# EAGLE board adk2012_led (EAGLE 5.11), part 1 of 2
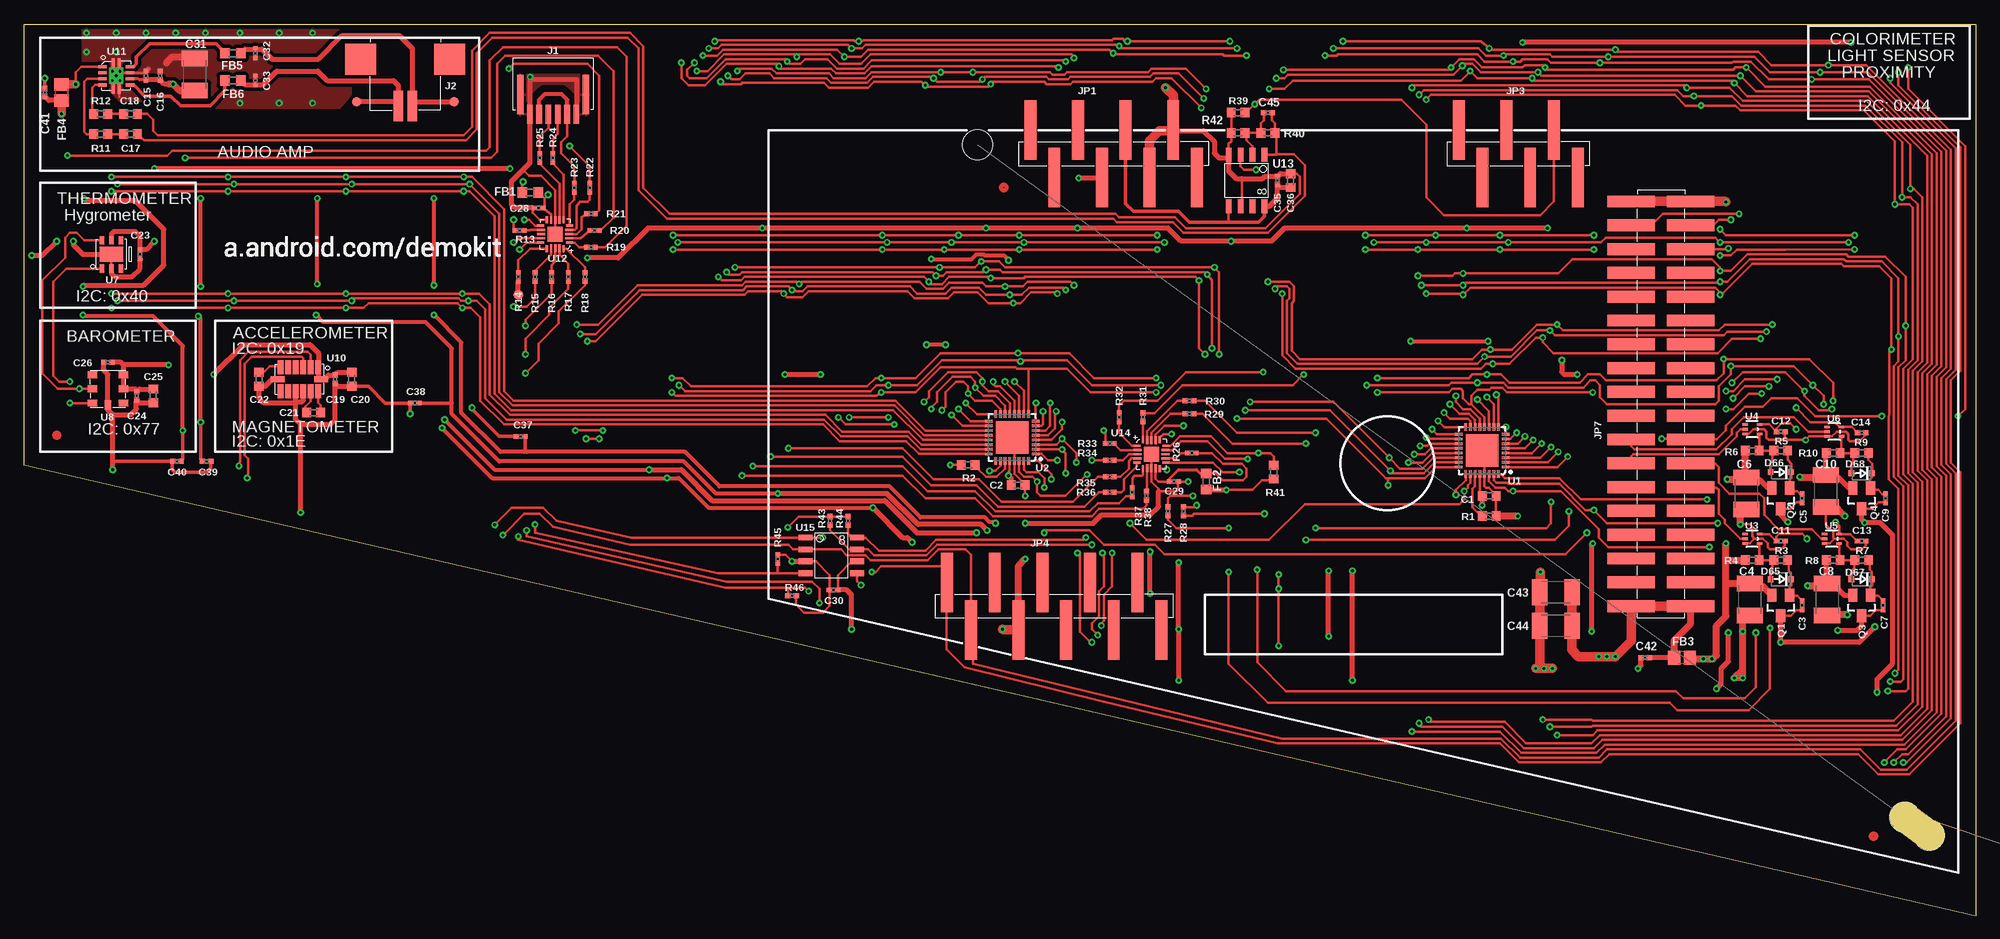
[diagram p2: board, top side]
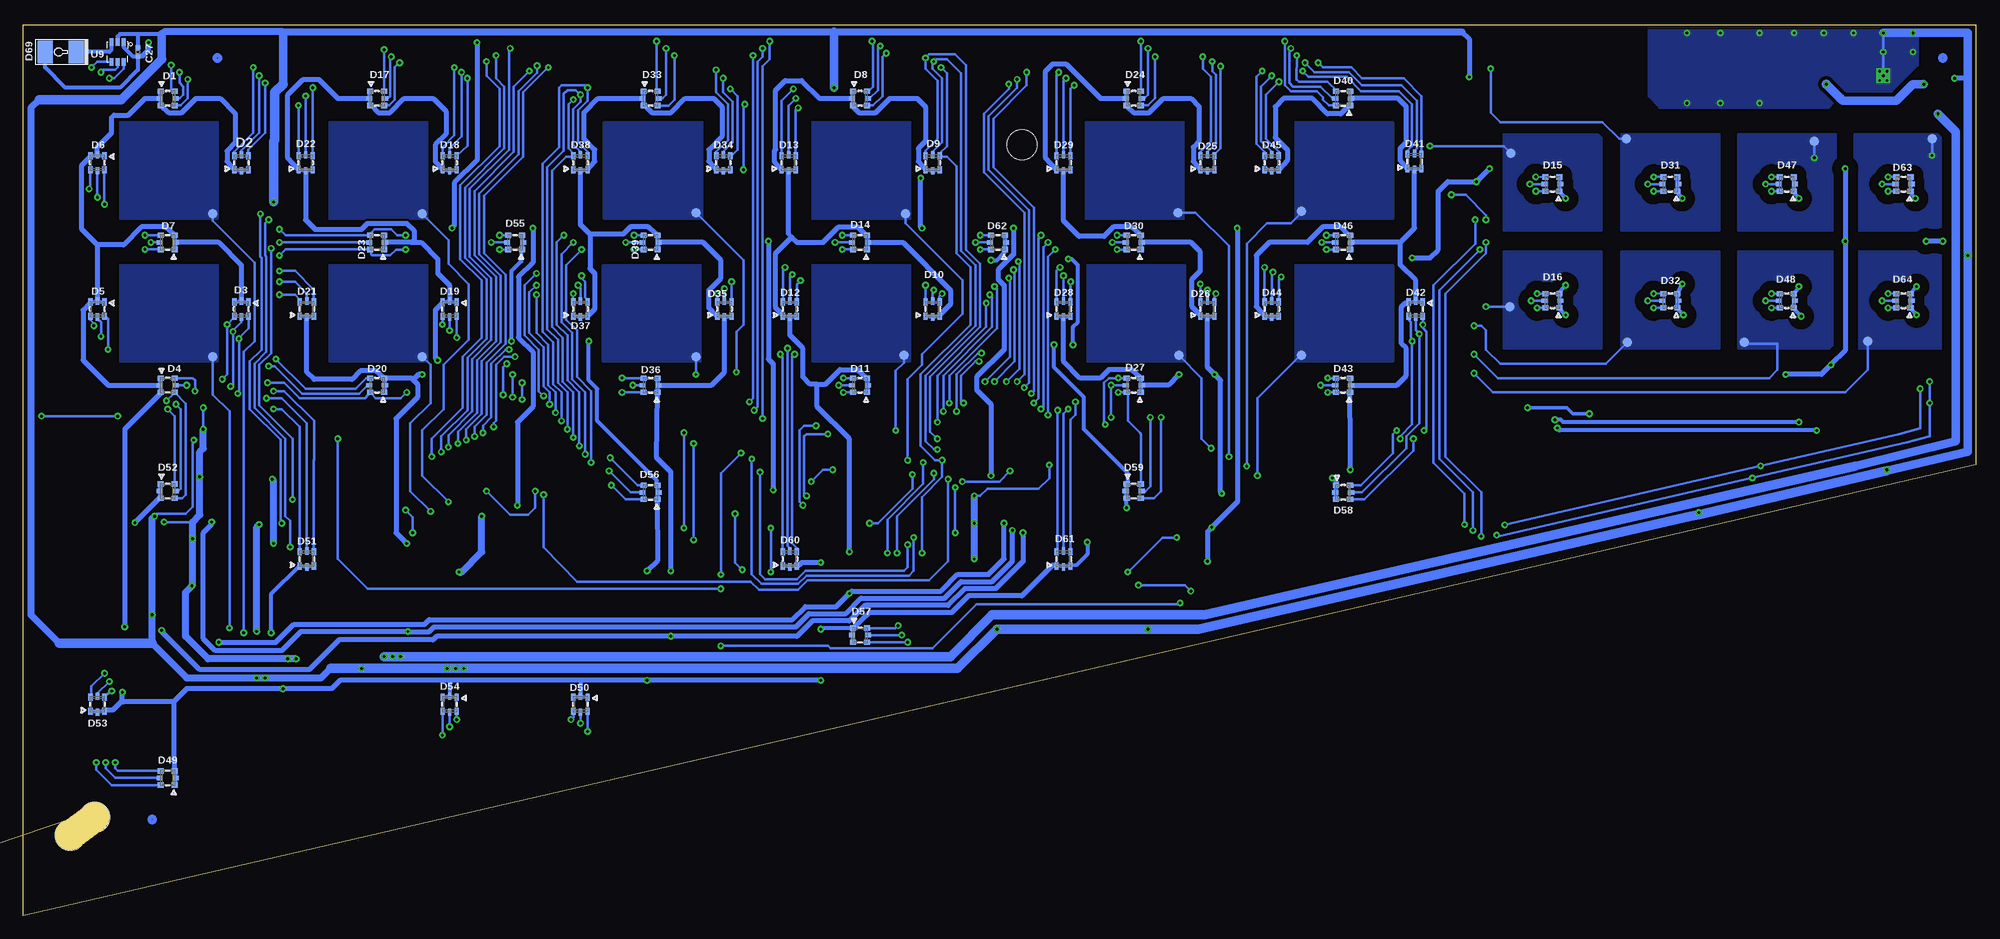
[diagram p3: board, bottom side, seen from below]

Size 208.38 x 95.07 mm. Coordinates in mm from the lower left corner, seen from the top.
Outline: 0,48.11 208.38,0 208.38,95.07 0,95.07 0,48.11
Copper layers (1*16): Top 0.035mm / dielectric 1.5mm / Bottom 0.035mm
Design rules "default *": minimum track width 6mil, minimum drill 10mil, track to track 6mil, track to pad 6mil, pad to pad 6mil, via to via 6mil, smd to smd 6mil, copper to edge 5mil, drill to drill 8mil, minimum pad ring 6mil, minimum via ring 8mil, stop-mask expansion 4mil, vias tented up to drill 12mil, thermal gap 10mil
Net classes: 0 default: width 0.152 mm, drill 0.305 mm, clearance 0.152 mm
Holes 3.2 mm at 101.8,82.25 203.4,8.59 200.77,10.49 9.48,-18.69
Holes 0.3 mm at 9.48,-13.61
Milling: 2 lines

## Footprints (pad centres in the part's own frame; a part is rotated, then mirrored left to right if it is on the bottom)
C0603U = smd 0.94 x 1.016: 1 -0.737,0; 2 0.737,0
C0402U = smd 0.584 x 0.508: 1 -0.445,0; 2 0.445,0
C1210U = smd 1.651 x 2.794: 1 -1.714,0; 2 1.714,0
LRTB-98G = smd 0.5 x 0.7: 1 -0.75,-0.75; 3 0.75,-0.75; 4 0.75,0.75; 6 -0.75,0.75 | smd 0.4 x 0.7: 2 0,-0.85; 5 0,0.85
SOD323-R = smd 0.6 x 0.6: A 1.1,0; C -1.1,0
SFH4651 = smd 1.6 x 2.4: 1 -1.65,0; 2 1.65,0
FB0603 = smd 1 x 1.1: 1 -0.85,0; 2 0.85,0
FB0805 = smd 1.3 x 1.5: 1 -0.85,0; 2 0.85,0
FCI_HFW6R-2ST = smd 0.6 x 2: 1 -2.5,0; 2 -1.5,0; 3 -0.5,0; 4 0.5,0; 5 1.5,0; 6 2.5,0 | smd 0.7 x 4.2: S@1 -3.5,-2.1; S@2 3.5,-2.1
MOLEX_292228-2 = smd 1 x 3.3: 1 -0.75,5; 2 0.75,5 | smd 3.3 x 3.3: P1 -4.75,0; P2 4.75,0
SULLINS_GEC08SABN = smd 1.27 x 6.35: 1 -8.89,2.54; 2 -6.35,-2.54; 3 -3.81,2.54; 4 -1.27,-2.54; 5 1.27,2.54; 6 3.81,-2.54; 7 6.35,2.54; 8 8.89,-2.54
SULLINS_GEC06SABN = smd 1.27 x 6.35: 1 -6.35,2.54; 2 -3.81,-2.54; 3 -1.27,2.54; 4 1.27,-2.54; 5 3.81,2.54; 6 6.35,-2.54
SULLINS_GEC10SABN = smd 1.27 x 6.35: 1 -11.43,2.54; 2 -8.89,-2.54; 3 -6.35,2.54; 4 -3.81,-2.54; 5 -1.27,2.54; 6 1.27,-2.54; 7 3.81,2.54; 8 6.35,-2.54; 9 8.89,2.54; 10 11.43,-2.54
SULLINS_GEC18DABN = smd 1.27 x 5.08: 1 -21.59,3.175; 2 -21.59,-3.175; 3 -19.05,3.175; 4 -19.05,-3.175; 5 -16.51,3.175; 6 -16.51,-3.175; 7 -13.97,3.175; 8 -13.97,-3.175; 9 -11.43,3.175; 10 -11.43,-3.175; 11 -8.89,3.175; 12 -8.89,-3.175; 13 -6.35,3.175; 14 -6.35,-3.175; 15 -3.81,3.175; 16 -3.81,-3.175; 17 -1.27,3.175; 18 -1.27,-3.175; 19 1.27,3.175; 20 1.27,-3.175; 21 3.81,3.175; 22 3.81,-3.175; 23 6.35,3.175; 24 6.35,-3.175; 25 8.89,3.175; 26 8.89,-3.175; 27 11.43,3.175; 28 11.43,-3.175; 29 13.97,3.175; 30 13.97,-3.175; 31 16.51,3.175; 32 16.51,-3.175; 33 19.05,3.175; 34 19.05,-3.175; 35 21.59,3.175; 36 21.59,-3.175
CAP_SENSE1 = smd 1 x 1: P$1 0,0
SUPER-SOT3 = smd 1 x 1.4: 1 -0.95,-1.1; 2 0.95,-1.1; 3 0,1.1
R0603U = smd 0.94 x 1.016: 1 -0.737,0; 2 0.737,0
R0402U = smd 0.584 x 0.508: 1 -0.445,0; 2 0.445,0
TP10R = smd 1 x 1: TP 0,0
QFN32-RHB = smd 0.8 x 0.3: 1 -2.5,1.75; 2 -2.5,1.25; 3 -2.5,0.75; 4 -2.5,0.25; 5 -2.5,-0.25; 6 -2.5,-0.75; 7 -2.5,-1.25; 8 -2.5,-1.75; 17 2.5,-1.75; 18 2.5,-1.25; 19 2.5,-0.75; 20 2.5,-0.25; 21 2.5,0.25; 22 2.5,0.75; 23 2.5,1.25; 24 2.5,1.75 | smd 0.3 x 0.8: 9 -1.75,-2.5; 10 -1.25,-2.5; 11 -0.75,-2.5; 12 -0.25,-2.5; 13 0.25,-2.5; 14 0.75,-2.5; 15 1.25,-2.5; 16 1.75,-2.5; 25 1.75,2.5; 26 1.25,2.5; 27 0.75,2.5; 28 0.25,2.5; 29 -0.25,2.5; 30 -0.75,2.5; 31 -1.25,2.5; 32 -1.75,2.5 | smd 3.45 x 3.45: PAD 0,0
SOT-553 = smd 0.3 x 0.6: 1 -0.5,-0.775; 2 0,-0.775; 3 0.5,-0.775; 4 0.5,0.775; 5 -0.5,0.775
SHT25 = smd 0.5 x 0.9: 1 1,1.5; 2 0,1.5; 3 -1,1.5; 4 -1,-1.5; 5 0,-1.5; 6 1,-1.5 | smd 2.5 x 1.6: EP 0,0
BMP180 = smd 1 x 0.7: 1 -1.65,1.5; 2 -1.65,0; 3 -1.65,-1.5; 4 1.65,-1.5; 5 1.65,0; 6 1.65,1.5 | smd 0.7 x 1: 7 0,1.75
OTDFN-6 = smd 0.4 x 0.8: 1 0.65,1.05; 2 0,1.05; 3 -0.65,1.05; 4 -0.65,-1.05; 5 0,-1.05; 6 0.65,-1.05
LGA35-14 = smd 0.6 x 1.5: 1 2,1.3; 2 1.2,1.3; 3 0.4,1.3; 4 -0.4,1.3; 5 -1.2,1.3; 6 -2,1.3; 8 -2,-1.3; 9 -1.2,-1.3; 10 -0.4,-1.3; 11 0.4,-1.3; 12 1.2,-1.3; 13 2,-1.3 | smd 1.5 x 0.6: 7 -2.3,0; 14 2.3,0
DFN3030-8 = smd 0.35 x 0.9: 1 0.975,1.475; 2 0.325,1.475; 3 -0.325,1.475; 4 -0.975,1.475; 5 -0.975,-1.475; 6 -0.325,-1.475; 7 0.325,-1.475; 8 0.975,-1.475 | smd 1.025 x 0.28: EP@1 -1.38,0.325; EP@2 -1.38,-0.325; EP@3 1.38,0.325; EP@4 1.38,-0.325 | smd 1.75 x 1.5: EP@5 0,0 | drill 0.305 pad 1.5 square: EP@6 0,0 | drill 0.305 pad 0.356 square: EP@7 -0.5,0.4; EP@8 0.5,0.4; EP@9 -0.5,-0.4; EP@10 0.5,-0.4
VQFN3030-20 = smd 0.75 x 0.25: 1 -1.55,0.9; 5 -1.55,-0.9; 11 1.55,-0.9; 15 1.55,0.9 | smd 0.85 x 0.25: 2 -1.5,0.45; 3 -1.5,0; 4 -1.5,-0.45; 12 1.5,-0.45; 13 1.5,0; 14 1.5,0.45 | smd 0.25 x 0.75: 6 -0.9,-1.55; 10 0.9,-1.55; 16 0.9,1.55; 20 -0.9,1.55 | smd 0.25 x 0.85: 7 -0.45,-1.5; 8 0,-1.5; 9 0.45,-1.5; 17 0.45,1.5; 18 0,1.5; 19 -0.45,1.5 | smd 1.6 x 1.6: EP 0,0
SO-8 = smd 1.524 x 0.61: 1 -2.743,1.27; 2 -2.743,0; 3 -2.743,-1.27; 4 -2.743,-2.54; 5 2.743,-2.54; 6 2.743,-1.27; 7 2.743,0; 8 2.743,1.27

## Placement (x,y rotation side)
C1  1uF  [C0603U]  156.41,44.78 0 top
C2  1uF  [C0603U]  106.12,45.92 0 top
C3  0.1uF  [C0402U]  189.81,33.1 90 top
C4  47uF 10V  [C1210U]  184.23,33.73 270 top
C5  0.1uF  [C0402U]  189.81,44.53 90 top
C6  47uF 10V  [C1210U]  183.85,45.03 270 top
C7  0.1uF  [C0402U]  198.45,33.1 90 top
C8  47uF 10V  [C1210U]  192.48,33.73 270 top
C9  0.1uF  [C0402U]  198.7,44.53 90 top
C10  47uF 10V  [C1210U]  192.35,45.29 270 top
C11  0.1uF  [C0402U]  187.53,39.95 0 top
C12  0.1uF  [C0402U]  187.53,51.64 0 top
C13  0.1uF  [C0402U]  196.16,39.95 0 top
C14  0.1uF  [C0402U]  196.16,51.51 0 top
C15  0.01uF  [C0402U]  13.03,89.61 90 top
C16  0.1uF  [C0402U]  14.55,89.61 90 top
C17  0.022uF  [C0603U]  11.38,83.39 0 top
C18  0.022uF  [C0603U]  11.38,85.55 0 top
C19  0.1uF  [C0402U]  33.22,57.23 270 top
C20  10uF  [C0603U]  35,57.23 270 top
C21  0.22uF  [C0603U]  30.94,53.67 0 top
C22  10uF  [C0603U]  25.1,57.23 270 top
C23  0.1uF  [C0402U]  12.4,70.56 270 top
C24  0.1uF  [C0402U]  12.04,55.45 270 top
C25  10uF  [C0603U]  13.82,55.45 270 top
C26  0.1uF  [C0402U]  8.97,59.03 180 top
C27  0.1uF  [C0402U]  196.16,92.15 90 bottom
C28  0.1uF  [C0402U]  54.94,75.51 180 top
C29  0.1uF  [C0402U]  122.76,46.3 0 top
C30  0.1uF  [C0402U]  86.44,34.75 0 top
C31  47uF 10V  [C1210U]  18.24,89.74 90 top
C32  0.01uF  [C0402U]  24.71,92.02 270 top
C33  0.01uF  [C0402U]  24.71,89.1 90 top
C35  0.01uF  [C0402U]  133.81,78.44 90 top
C36  1uF  [C0603U]  135.2,78.44 90 top
C37  0.1uF  [C0402U]  53.04,51.13 180 top
C38  0.1uF  [C0402U]  41.73,54.69 180 top
C39  0.1uF  [C0402U]  19.51,48.46 0 top
C40  0.1uF  [C0402U]  16.33,48.46 180 top
C41  0.01uF  [C0402U]  2.24,87.83 90 top
C42  0.01uF  [C0402U]  173.05,27.51 180 top
C43  DNI  [C1210U]  163.53,34.49 180 top
C44  DNI  [C1210U]  163.53,30.94 180 top
C45  DNI  [C0402U]  132.79,85.67 180 top
D1  LRTB-R98G  [LRTB-98G]  192.99,87.2 270 bottom
D2  LRTB-R98G  [LRTB-98G]  185.12,80.34 0 bottom
D3  LRTB-R98G  [LRTB-98G]  185.12,64.72 180 bottom
D4  LRTB-R98G  [LRTB-98G]  192.99,56.59 270 bottom
D5  LRTB-R98G  [LRTB-98G]  200.48,64.72 180 bottom
D6  LRTB-R98G  [LRTB-98G]  200.48,80.34 180 bottom
D7  LRTB-R98G  [LRTB-98G]  192.99,71.83 90 bottom
D8  LRTB-R98G  [LRTB-98G]  119.08,87.2 270 bottom
D9  LRTB-R98G  [LRTB-98G]  111.33,80.34 0 bottom
D10  LRTB-R98G  [LRTB-98G]  111.33,64.72 0 bottom
D11  LRTB-R98G  [LRTB-98G]  119.08,56.59 90 bottom
D12  LRTB-R98G  [LRTB-98G]  126.57,64.72 0 bottom
D13  LRTB-R98G  [LRTB-98G]  126.7,80.34 0 bottom
D14  LRTB-R98G  [LRTB-98G]  119.08,71.83 90 bottom
D15  LRTB-R98G  [LRTB-98G]  45.16,78.05 90 bottom
D16  LRTB-R98G  [LRTB-98G]  45.16,65.61 90 bottom
D17  LRTB-R98G  [LRTB-98G]  170.64,87.2 270 bottom
D18  LRTB-R98G  [LRTB-98G]  162.89,80.34 0 bottom
D19  LRTB-R98G  [LRTB-98G]  162.89,64.72 180 bottom
D20  LRTB-R98G  [LRTB-98G]  170.64,56.59 90 bottom
D21  LRTB-R98G  [LRTB-98G]  178.13,64.72 0 bottom
D22  LRTB-R98G  [LRTB-98G]  178.26,80.34 0 bottom
D23  LRTB-R98G  [LRTB-98G]  170.64,71.83 90 bottom
D24  LRTB-R98G  [LRTB-98G]  89.87,87.2 270 bottom
D25  LRTB-R98G  [LRTB-98G]  81.99,80.34 0 bottom
D26  LRTB-R98G  [LRTB-98G]  81.99,64.72 0 bottom
D27  LRTB-R98G  [LRTB-98G]  89.87,56.59 90 bottom
D28  LRTB-R98G  [LRTB-98G]  97.36,64.72 0 bottom
D29  LRTB-R98G  [LRTB-98G]  97.36,80.34 0 bottom
D30  LRTB-R98G  [LRTB-98G]  89.87,71.83 90 bottom
D31  LRTB-R98G  [LRTB-98G]  32.59,78.05 90 bottom
D32  LRTB-R98G  [LRTB-98G]  32.59,65.61 90 bottom
D33  LRTB-R98G  [LRTB-98G]  141.43,87.2 270 bottom
D34  LRTB-R98G  [LRTB-98G]  133.68,80.34 0 bottom
D35  LRTB-R98G  [LRTB-98G]  133.55,64.72 0 bottom
D36  LRTB-R98G  [LRTB-98G]  141.43,56.59 90 bottom
D37  LRTB-R98G  [LRTB-98G]  148.92,64.72 0 bottom
D38  LRTB-R98G  [LRTB-98G]  148.92,80.34 0 bottom
D39  LRTB-R98G  [LRTB-98G]  141.43,71.83 90 bottom
D40  LRTB-R98G  [LRTB-98G]  67.51,87.2 90 bottom
D41  LRTB-R98G  [LRTB-98G]  59.89,80.47 0 bottom
D42  LRTB-R98G  [LRTB-98G]  59.77,64.72 180 bottom
D43  LRTB-R98G  [LRTB-98G]  67.51,56.59 90 bottom
D44  LRTB-R98G  [LRTB-98G]  75.13,64.72 0 bottom
D45  LRTB-R98G  [LRTB-98G]  75.13,80.34 0 bottom
D46  LRTB-R98G  [LRTB-98G]  67.51,71.83 90 bottom
D47  LRTB-R98G  [LRTB-98G]  20.14,78.05 90 bottom
D48  LRTB-R98G  [LRTB-98G]  20.14,65.61 90 bottom
D49  LRTB-R98G  [LRTB-98G]  192.99,14.68 90 bottom
D50  LRTB-R98G  [LRTB-98G]  148.92,22.56 180 bottom
D51  LRTB-R98G  [LRTB-98G]  178.13,38.05 0 bottom
D52  LRTB-R98G  [LRTB-98G]  192.99,45.29 270 bottom
D53  LRTB-R98G  [LRTB-98G]  200.48,22.56 0 bottom
D54  LRTB-R98G  [LRTB-98G]  162.89,22.56 180 bottom
D55  LRTB-R98G  [LRTB-98G]  155.91,71.83 90 bottom
D56  LRTB-R98G  [LRTB-98G]  141.43,45.16 90 bottom
D57  LRTB-R98G  [LRTB-98G]  119.08,29.92 270 bottom
D58  LRTB-R98G  [LRTB-98G]  67.51,45.16 270 bottom
D59  LRTB-R98G  [LRTB-98G]  89.87,45.29 270 bottom
D60  LRTB-R98G  [LRTB-98G]  126.57,38.05 0 bottom
D61  LRTB-R98G  [LRTB-98G]  97.36,38.05 0 bottom
D62  LRTB-R98G  [LRTB-98G]  104.34,71.83 90 bottom
D63  LRTB-R98G  [LRTB-98G]  7.7,78.05 90 bottom
D64  LRTB-R98G  [LRTB-98G]  7.7,65.61 90 bottom
D65  1N4148  [SOD323-R]  187.53,35.89 180 top
D66  1N4148  [SOD323-R]  187.53,47.32 180 top
D67  1N4148  [SOD323-R]  196.16,35.89 180 top
D68  1N4148  [SOD323-R]  196.16,47.19 180 top
D69  SFH4651  [SFH4651]  204.42,92.15 0 bottom
FB1  HZ0603B102R-10  [FB0603]  54.05,77.17 180 top
FB2  HZ0603B102R-10  [FB0603]  126.19,46.3 270 top
FB3  MI0805J102R-10  [FB0805]  176.99,27.51 180 top
FB4  MI0805J102R-10  [FB0805]  4.01,87.83 270 top
FB5  MI0603J601R-10  [FB0603]  22.3,92.02 0 top
FB6  MI0603J601R-10  [FB0603]  22.3,89.1 0 top
J1  [FCI_HFW6R-2ST]  56.49,85.5 180 top
J2  MOLEX_292228-2  [MOLEX_292228-2]  40.72,91.39 180 top
JP1  [SULLINS_GEC08SABN]  116.33,81.28 0 top
JP3  [SULLINS_GEC06SABN]  159.51,81.28 0 top
JP4  [SULLINS_GEC10SABN]  109.98,33.02 0 top
JP7  [SULLINS_GEC18DABN]  174.75,54.61 90 top
P1  KEY  [CAP_SENSE1]  49.61,81.36 90 bottom
P2  KEY  [CAP_SENSE1]  37.29,82.88 90 bottom
P3  KEY  [CAP_SENSE1]  17.22,82.63 90 bottom
P4  KEY  [CAP_SENSE1]  4.65,82.88 90 bottom
P5  KEY  [CAP_SENSE1]  11.51,61.29 90 bottom
P6  KEY  [CAP_SENSE1]  24.71,61.16 90 bottom
P7  KEY  [CAP_SENSE1]  37.16,61.16 90 bottom
P8  KEY  [CAP_SENSE1]  49.73,64.97 90 bottom
P9  KEY  [CAP_SENSE1]  52.78,66.24 90 top
P10  KEY  [CAP_SENSE1]  71.96,59.77 270 bottom
P11  KEY  [CAP_SENSE1]  71.96,75.13 270 bottom
P12  KEY  [CAP_SENSE1]  85.17,75.01 270 bottom
P13  KEY  [CAP_SENSE1]  85.04,59.77 270 bottom
P14  KEY  [CAP_SENSE1]  114.25,74.88 270 bottom
P15  KEY  [CAP_SENSE1]  114.38,59.77 270 bottom
P16  KEY  [CAP_SENSE1]  136.6,75.01 270 bottom
P17  KEY  [CAP_SENSE1]  136.6,59.64 270 bottom
P18  KEY  [CAP_SENSE1]  165.81,74.88 270 bottom
P19  KEY  [CAP_SENSE1]  165.81,59.64 270 bottom
P20  KEY  [CAP_SENSE1]  188.16,74.88 270 bottom
P21  KEY  [CAP_SENSE1]  188.16,59.64 270 bottom
Q1  DMP2035U-7  [SUPER-SOT3]  187.53,33.1 180 top
Q2  DMP2035U-7  [SUPER-SOT3]  187.53,44.53 180 top
Q3  DMP2035U-7  [SUPER-SOT3]  196.16,33.1 180 top
Q4  DMP2035U-7  [SUPER-SOT3]  196.16,44.53 180 top
R1  4.99k  [R0603U]  156.41,42.62 180 top
R2  4.99k  [R0603U]  100.79,48.08 0 top
R3  470R  [R0603U]  187.53,37.92 0 top
R4  2K49  [R0603U]  184.48,37.92 180 top
R5  470R  [R0603U]  187.53,49.61 0 top
R6  2K49  [R0603U]  184.48,49.61 180 top
R7  470R  [R0603U]  196.16,37.92 0 top
R8  2K49  [R0603U]  193.12,37.92 180 top
R9  470R  [R0603U]  196.16,49.35 0 top
R10  2K49  [R0603U]  193.12,49.35 180 top
R11  150K  [R0603U]  8.2,83.39 0 top
R12  150K  [R0603U]  8.2,85.55 0 top
R13  10K  [R0402U]  52.91,73.1 180 top
R14  10K  [R0402U]  52.78,68.15 90 top
R15  10K  [R0402U]  54.56,68.15 90 top
R16  10K  [R0402U]  56.34,68.15 90 top
R17  10K  [R0402U]  58.12,68.15 90 top
R18  10K  [R0402U]  59.89,68.15 90 top
R19  10K  [R0402U]  60.53,71.32 180 top
R20  10K  [R0402U]  60.91,73.1 180 top
R21  10K  [R0402U]  60.53,74.88 180 top
R22  10K  [R0402U]  60.4,77.67 270 top
R23  10K  [R0402U]  58.75,77.67 270 top
R24  10K  [R0402U]  56.46,80.85 270 top
R25  10K  [R0402U]  55.07,80.85 270 top
R26  10K  [R0402U]  124.66,49.35 0 top
R27  10K  [R0402U]  122.12,43.13 90 top
R28  10K  [R0402U]  123.77,43.13 90 top
R29  10K  [R0402U]  124.41,53.54 180 top
R30  10K  [R0402U]  124.41,54.94 180 top
R31  10K  [R0402U]  119.46,53.16 270 top
R32  10K  [R0402U]  116.92,53.16 270 top
R33  10K  [R0402U]  115.9,50.37 0 top
R34  10K  [R0402U]  115.9,48.59 0 top
R35  10K  [R0402U]  115.9,46.81 0 top
R36  10K  [R0402U]  115.9,45.16 0 top
R37  10K  [R0402U]  118.31,45.16 90 top
R38  10K  [R0402U]  119.84,44.78 90 top
R39  10K  [R0603U]  129.62,85.67 0 top
R40  10K  [R0603U]  132.79,83.52 0 top
R41  10K  [R0603U]  133.41,47.31 270 top
R42  22K  [R0603U]  129.62,83.52 0 top
R43  10K  [R0402U]  86.06,42.11 90 top
R44  10K  [R0402U]  87.96,42.11 90 top
R45  10K  [R0402U]  80.47,38.05 90 top
R46  10K  [R0402U]  81.99,34.11 0 top
TP1  TPTP10R  [TP10R]  45.92,86.82 0 top
TP2  TPTP10R  [TP10R]  35.51,86.82 0 top
U1  TLC5947  [QFN32-RHB]  155.65,49.61 180 top
U2  TLC5947  [QFN32-RHB]  105.49,51 180 top
U3  74LV1G17  [SOT-553]  184.48,40.21 270 top
U4  74LV1G17  [SOT-553]  184.48,51.89 270 top
U5  74LV1G17  [SOT-553]  192.99,40.21 270 top
U6  74LV1G17  [SOT-553]  193.24,51.64 270 top
U7  SHT25  [SHT25]  9.35,70.56 180 top
U8  BMP180  [BMP180]  8.97,56.21 180 top
U9  MAX44005  [OTDFN-6]  198.32,92.15 0 bottom
U10  LSM303DLHC  [LGA35-14]  29.41,57.23 0 top
U11  TPA2006D1  [DFN3030-8]  9.86,89.61 90 top
U12  AT42QT2120  [VQFN3030-20]  56.72,72.72 180 top
U13  MCP6L02T-E  [SO-8]  131.14,78.44 270 top
U14  AT42QT2120  [VQFN3030-20]  120.35,49.23 0 top
U15  PCA9540BD  [SO-8]  86.18,39.07 0 top
U$2  [A3L-LOC]  not placed on the board
U$3  [FIDUCIAL_R]  3.51,51.26 0 top
U$4  [FIDUCIAL_R]  104.6,77.67 0 top
U$5  [FIDUCIAL_R]  197.43,8.46 0 top
U$6  [FIDUCIAL_R]  3.51,91.52 0 bottom
U$7  [FIDUCIAL_R]  187.66,91.52 0 bottom
U$8  [FIDUCIAL_R]  194.64,10.24 0 bottom
U$9  [ADK2_URL]  21.29,70.05 0 top

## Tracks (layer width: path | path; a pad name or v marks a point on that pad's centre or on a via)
5V_2
  Top 0.254: 128.6,73.99 U13.5
  Top 0.381: JP1.5 117.6,75.97 118.44,75.13 123.27,75.13 124.41,73.99 128.6,73.99 131.78,73.99 132.41,74.63 U13.8
  Top 0.508: U13.8 132.97,75.69 133.81,76.53 C35.1 134.1,77.7 C36.1
+3V3  (via drill 0.3)
  Top 0.254: U1.28 155.4,44.82 C1.1 | C2.1 105.24,45.96 | U15.3 83.52,37.8 84.53,37.8 85.99,36.34 C30.1 85.99,33.03 85.29,32.33 83.26,32.33 82.44,33.16 R46.2 | C25.1 14.03,56.08 | v128.35,45.42 131.14,45.42 132.16,46.43 133.38,46.43 R41.2 | 53.33,78.27 v53.29,78.31 53.2,78.22 FB1.2 | U2.28 105.23,47.45 105.11,47.32 v105.11,46.94 | R44.2 R43.2 82.69,42.56 v81.55,41.42 | v81.99,37.8 81.29,38.49 R45.2
  Top 0.508: JP1.4 112.65,78.74 v112.6,78.69 | v60.15,70.18 63.45,70.18 66.62,73.36 v78.82,73.36 v102.69,73.36 v112.47,73.36 122.12,73.36 123.52,71.96 v128.85,71.96 133.17,71.96 134.57,73.36 v154,73.36 v162.64,73.36 | v51.89,79.71 v13.92,79.71 | v13.92,71.96 13.03,71.07 12.41,71.07 C23.1 12.4,72.47 11.89,72.97 9.6,72.97 9.35,72.72 U7.5 | 13.62,56.1 C25.1 12.33,56.19 C24.1 11.93,56.21 U8.2 U8.3 10.62,58.75 | C26.1 10.34,59.03 10.62,58.75 | v15.44,58.75 10.62,58.75 | v195.02,93.17 v159.97,93.17 | v128.35,45.42 128.36,45.4 126.34,45.4 FB2.2 | v81.99,37.8 83.52,37.8 | v20.27,57.73 23.44,60.91 30.56,60.91 31.45,60.02 31.45,58.56 U10.1 31.41,57.53 U10.14 32.08,57.23 32.53,57.67 C19.1 33.52,57.96 C20.1 34.8,57.88 | v105.11,46.94 105.38,46.66 C2.1 | v155.65,43.76 155.68,43.79 C1.1
  Bottom 0.406: D69.1 206.07,90.5 203.91,88.34 198.07,88.34 196.16,90.25 C27.1 196.18,91.64 196.67,91.64 197.67,92.64 U9.1
  Bottom 0.508: v112.6,78.69 112.6,73.48 v112.47,73.36 | v60.15,70.18 58.24,70.18 57.35,71.07 57.35,77.29 56.34,78.31 v53.29,78.31 v51.89,79.71 | v155.65,43.76 155.65,52.65 154,54.31 154,60.15 155.52,61.67 155.52,68.15 154,69.67 v154,73.36 | v105.11,46.94 105.11,54.56 106.63,56.08 106.63,57.48 103.71,60.4 103.71,67.26 104.34,67.89 104.34,68.91 102.69,70.56 v102.69,73.36 | v13.92,79.71 v13.92,71.96 13.92,60.27 v15.44,58.75 16.46,57.73 v20.27,57.73 | v195.02,93.17 195.02,92.41 195.72,91.71 C27.1 | v159.97,93.17 159.97,80.59 162.38,78.18 162.38,73.61 v162.64,73.36 | v128.35,45.42 128.35,58.88 128.85,59.39 v128.85,71.96 | v81.99,37.8 81.99,40.97 v81.55,41.42 81.48,41.48 78.82,44.15 v78.82,73.36
+5V  (via drill 0.3)
  Top 0.508: FB3.2 C42.1 | C41.1 2.64,86.98 FB4.2
  Top 0.762: FB3.2 176.14,29.33 177.88,31.06 177.88,32.97 JP7.2
  Top 0.889: v4.01,85.55 FB4.2
  Top 1.016: JP7.2 JP7.1 171.58,29.34 v169.88,27.64 v168.99,27.64 v168.1,27.64 165.94,27.64 165.24,28.33 C44.1 C43.1
  Bottom 0.889: 12.9,47.96 2.11,50.62 2.11,83.64 v4.01,85.55
  Bottom 1.016: v169.88,27.64 v168.99,27.64 v168.1,27.64 109.42,27.64 104.98,32.08 82.25,32.08 46.43,40.34 12.9,47.96
B0
  Top 0.254: JP7.12 177.98,45.67 180.67,45.67 180.92,45.42 180.92,42.88 181.56,42.24 181.56,41.86 183.21,40.21 U3.2
B1
  Top 0.254: JP7.13 171.58,49.02 171.78,49.23 180.92,49.23 182.83,51.13 182.83,51.51 183.21,51.89 U4.2
B2
  Top 0.254: JP7.14 177.98,48.21 180.54,48.21 180.92,47.83 180.92,46.18 182.07,45.03 185.24,45.03 185.75,44.53 185.75,42.75 187.27,41.22 190.83,41.22 191.85,40.21 U5.2
B3
  Top 0.254: JP7.15 171.58,50.06 171.91,49.73 180.67,49.73 182.32,51.38 182.32,51.89 183.59,53.16 188.93,53.16 190.45,51.64 U6.2
BANK0-
  Top 0.254: D65.A 186.43,36.7 186.64,36.91 186.64,37.88 R3.1 R4.1 | R4.1 185.16,38.1 | U3.4 185.26,38 R4.1
BANK1-
  Top 0.254: R6.1 185.16,49.78 | R6.1 R5.1 186.64,49.57 186.64,48.46 186.43,48.25 D66.A | U4.4 185.26,49.68 R6.1
BANK2-
  Top 0.254: D67.A 195.06,36.7 195.4,37.03 195.4,37.83 R7.1 R8.1 | R8.1 193.79,38.1 | U5.4 193.76,38.12 R8.1
BANK2-1
  Top 0.254: D68.A 195.06,48.13 195.28,48.34 195.28,49.31 R9.1 R10.1 | R10.1 193.79,49.53 | U6.4 194.02,49.4 R10.1
DAC0  (via drill 0.3)
  Top 0.254: JP3.5 163.32,76.2 161.87,74.75 151.59,74.75 149.68,76.66 149.68,84.4 147.02,87.07 131.86,87.07 131.76,86.96 v131.38,86.58 130.47,85.67 R39.2 130.35,85.56 | U13.3 129.87,79.96 130.25,79.58 v131.52,79.58
  Bottom 0.254: v131.52,79.58 131.52,86.44 v131.38,86.58
DRVA0  (via drill 0.3)
  Top 0.254: v138.89,91.77 140.16,91.77 140.28,91.9 155.14,91.9 155.91,91.14 v158.95,91.14 159.72,91.14 159.97,91.39 162.64,91.39 163.02,91.01 v168.22,91.01 182.32,91.01 182.45,91.14 184.35,91.14 186.26,89.23 v190.83,89.23 196.93,89.23 204.67,81.48 204.67,58.62 203.66,57.61 203.66,47.83 204.67,46.81 204.67,21.54 200.86,17.73 199.97,17.73 v198.58,16.33 | U1.1 163.68,47.86 v164.8,48.97
  Bottom 0.254: D1.4 191.58,86.45 190.83,87.2 v190.83,89.23 | v138.89,91.77 138.89,87.07 139.52,86.44 140.77,86.44 D33.4 | D17.4 169.36,86.45 168.73,87.07 168.73,90.5 v168.22,91.01 | D49.4 198.31,15.43 198.58,15.7 v198.58,16.33 | v164.8,48.97 164.8,50.88 161.49,54.18 161.49,59.64 159.46,61.67 159.46,67.77 161.75,70.05 161.75,77.93 157.56,82.12 157.56,88.21 158.95,89.61 v158.95,91.14
DRVA1  (via drill 0.3)
  Top 0.254: v139.78,92.53 155.27,92.53 156.03,91.77 v157.94,91.77 158.06,91.9 162.89,91.9 163.14,91.64 v169.11,91.64 184.73,91.64 186.39,89.99 v191.72,89.99 196.8,89.99 205.18,81.61 205.18,58.5 204.17,57.48 204.17,47.96 205.18,46.94 205.18,21.29 201.12,17.22 200.48,17.22 v199.59,16.33 | U1.2 162.66,48.36 v163.78,49.48
  Bottom 0.254: D1.5 191.72,87.2 191.34,87.58 191.34,88.47 191.72,88.85 v191.72,89.99 | v139.78,92.53 139.78,87.58 140.16,87.2 D33.5 | D17.5 169.49,87.2 169.24,87.45 169.24,91.52 v169.11,91.64 | v199.59,16.33 199.59,15.7 198.58,14.68 D49.5 | v163.78,49.48 163.78,51.13 160.99,53.92 160.99,59.51 158.95,61.54 158.95,67.89 161.24,70.18 161.24,77.67 157.05,81.86 157.05,88.47 157.94,89.36 v157.94,91.77
DRVA2  (via drill 0.3)
  Top 0.254: v200.61,16.33 200.99,16.33 205.69,21.03 205.69,47.07 204.67,48.08 204.67,57.35 205.69,58.37 205.69,81.74 196.67,90.75 v192.61,90.75 186.51,90.75 185.12,92.15 170.13,92.15 v169.88,92.41 156.54,92.41 v156.41,92.53 155.52,93.29 v140.79,93.29 | U1.3 161.89,48.86 v163.02,49.99
  Bottom 0.254: D1.6 192.59,88.2 192.59,90.74 v192.61,90.75 | v140.79,93.29 140.79,87.96 D33.6 | D17.6 v169.88,92.41 169.99,92.29 | v200.61,16.33 200.61,15.57 198.96,13.92 193.65,13.92 D49.6 | v163.02,49.99 163.02,51.26 160.48,53.8 160.48,59.39 158.45,61.42 158.45,68.02 160.73,70.31 160.73,77.55 156.54,81.74 156.54,92.41 v156.41,92.53
DRVA3  (via drill 0.3)
  Top 0.254: v132.92,88.21 134.57,88.21 135.46,89.1 153.37,89.1 v154.38,90.12 155.14,89.36 v160.99,89.36 161.24,89.1 182.32,89.1 v182.58,88.85 183.97,87.45 196.8,87.45 203.15,81.1 203.15,59 202.13,57.99 202.13,47.45 203.15,46.43 203.15,22.05 200.36,19.25 168.22,19.25 167.34,18.36 160.35,18.36 158.06,20.65 150.19,20.65 v149.94,20.9 | U1.4 160.98,49.36 v162,50.37
  Bottom 0.254: D2.4 184.37,81.73 182.58,83.52 v182.58,88.85 | v160.99,89.36 160.99,82.15 D18.4 | D34.4 132.9,80.99 132.16,81.74 132.16,87.45 v132.92,88.21 132.93,88.2 | D50.4 149.67,21.17 v149.94,20.9 | v162,50.37 162,51.64 159.97,53.67 159.97,59.26 157.94,61.29 157.94,68.15 160.22,70.43 160.22,77.29 156.03,81.48 156.03,88.47 v154.38,90.12
DRVA4  (via drill 0.3)
  Top 0.254: v133.68,89.36 134.57,89.36 134.95,89.74 152.6,89.74 v153.56,90.69 153.75,90.88 154.64,90.88 155.52,89.99 v161.62,89.99 162,89.61 v183.21,89.61 184.86,87.96 196.93,87.96 203.66,81.23 203.66,58.88 202.64,57.86 202.64,47.57 203.66,46.56 203.66,21.92 200.48,18.75 168.48,18.75 167.59,17.86 160.1,17.86 157.81,20.14 149.17,20.14 148.92,20.4 v148.92,20.52 | U1.5 160.22,49.86 v161.11,50.75
  Bottom 0.254: D2.5 185.12,81.61 183.21,83.52 v183.21,89.61 | v161.62,89.99 161.62,83.13 162.89,81.86 D18.5 | v133.68,89.36 133.68,87.83 132.66,86.82 132.66,82.5 133.68,81.48 D34.5 | v148.92,20.52 D50.5 | v161.11,50.75 161.11,51.89 159.46,53.54 159.46,59.13 157.43,61.16 157.43,68.28 159.72,70.56 159.72,77.04 155.52,81.23 155.52,87.96 153.56,89.93 v153.56,90.69
DRVA5  (via drill 0.3)
  Top 0.254: v148.16,19.63 157.56,19.63 159.84,17.35 167.84,17.35 168.73,18.24 200.74,18.24 204.17,21.67 204.17,46.69 203.15,47.7 203.15,57.73 204.17,58.75 204.17,81.36 197.05,88.47 185.88,88.47 v183.85,90.5 182.7,90.5 182.45,90.25 162.64,90.25 v162.38,90.5 162.13,90.75 160.22,90.75 159.97,90.5 155.65,90.5 154.76,91.39 153.24,91.39 v152.35,90.5 152.1,90.25 v134.44,90.25 | U1.6 159.45,50.36 v160.22,51.13
  Bottom 0.254: v162.38,90.5 162.38,83.26 163.65,81.99 163.65,81 D18.6 | D34.6 134.43,81.5 133.17,82.75 133.17,86.56 134.44,87.83 v134.44,90.25 | v148.16,19.63 148.16,21.89 D50.6 | v160.22,51.13 160.22,52.15 158.95,53.42 158.95,59 156.92,61.04 156.92,68.4 159.21,70.69 159.21,76.78 155.02,80.98 155.02,87.83 v152.35,90.5 | v183.85,90.5 183.85,83.52 185.88,81.48 185.88,81 D2.6
DRVA6  (via drill 0.3)
  Top 0.254: v186.63,63.07 181.56,63.07 180.92,62.43 164.29,62.43 v163.65,63.07 161.49,63.07 158.83,60.4 v156.54,60.4 155.65,60.4 154.64,59.39 136.22,59.39 135.33,60.27 135.33,65.35 135.59,65.61 135.59,67.13 135.08,67.64 v132.79,67.64 | U1.7 158.68,50.86 v159.33,51.51 | v187.15,57.23 183.72,57.23 182.45,55.96 v181.69,55.96
  Bottom 0.254: D19.4 163.65,64.06 v163.65,63.07 | D3.4 185.87,63.84 186.64,63.07 v186.63,63.07 186.64,62.55 186.64,57.73 v187.15,57.23 | v132.79,67.64 132.79,65.38 D35.4 | v159.33,51.51 159.33,52.27 158.45,53.16 158.45,58.88 156.92,60.4 v156.54,60.4 | D51.4 177.38,48.6 177.37,48.59 177.37,52.78 180.54,55.96 v181.69,55.96
DRVA7  (via drill 0.3)
  Top 0.254: v186,62.31 181.81,62.31 181.43,61.93 163.4,61.93 v162.89,62.43 161.49,62.43 158.7,59.64 v155.91,59.64 155.14,58.88 135.97,58.88 134.82,60.02 134.82,65.61 135.08,65.86 135.08,66.88 134.82,67.13 133.81,67.13 v133.55,66.88 | U1.8 158.16,52.12 v158.19,52.15 | v186.26,56.46 183.72,56.46 v182.45,55.19
  Bottom 0.254: D3.5 185.12,63.32 186,62.43 v186,62.31 186,56.72 v186.26,56.46 | v162.89,62.43 D19.5 | v133.55,66.88 D35.5 | v158.19,52.15 158.19,52.53 157.94,52.78 157.94,58.75 157.05,59.64 v155.91,59.64 | v182.45,55.19 180.8,55.19 178.13,52.53 D51.5
DRVA8  (via drill 0.3)
  Top 0.254: U1.9 157.4,55.29 v157.18,55.58 | v134.32,66.37 134.32,59.77 135.71,58.37 155.52,58.37 156.03,58.88 v156.79,58.88 158.57,58.88 161.37,61.67 v162.13,61.67 162.13,61.16 163.27,60.02 180.8,60.02 182.32,61.54 v185.37,61.54 | v185.5,55.7 184.1,55.7 182.45,54.05 v181.69,54.05
  Bottom 0.254: D19.6 162.13,64.06 v162.13,61.67 | D3.6 184.35,64.06 184.35,62.69 185.37,61.67 v185.37,61.54 185.37,55.83 v185.5,55.7 | v134.32,66.37 134.32,65.38 D35.6 | v157.18,55.58 157.18,58.5 v156.79,58.88 | D51.6 178.88,45.91 178.89,45.92 178.89,52.15 180.8,54.05 v181.69,54.05
DRVA9  (via drill 0.3)
  Top 0.254: v193.12,54.94 193.12,56.85 190.58,59.39 v181.43,59.39 181.43,57.86 180.67,57.1 168.86,57.1 168.22,57.73 166.95,57.73 166.07,56.85 158.57,56.85 157.68,57.73 v156.16,57.73 154.64,57.73 154.25,57.35 v144.48,57.35 | U1.10 156.9,54.58 v156.16,55.32
  Bottom 0.254: v193.12,54.94 192.34,55.7 D4.4 191.08,54.59 191.08,44.91 191.45,44.54 D52.4 | D36.4 144.46,57.34 v144.48,57.35 | v156.16,57.73 v156.16,55.32 | v181.43,59.39 178.26,56.21 172.92,56.21 171.79,57.34 D20.4
DRVA10  (via drill 0.3)
  Top 0.254: U1.11 156.4,53.81 v155.14,55.07 | v143.33,56.59 152.1,56.59 152.35,56.85 v155.14,56.85 157.94,56.85 158.45,56.34 166.45,56.34 167.21,57.1 167.72,57.1 168.22,56.59 168.22,55.32 168.99,54.56 180.54,54.56 180.92,54.94 180.92,56.46 182.19,57.73 v182.19,58.62 188.93,58.62 v190.96,56.59 192.1,55.45 v192.1,54.56
  Bottom 0.254: v190.96,56.59 D4.5 | D36.5 v143.33,56.59 | v155.14,56.85 v155.14,55.07 | D52.5 191.85,45.29 191.59,45.54 191.59,54.05 v192.1,54.56 | D20.5 171.65,56.59 172.54,55.7 178.64,55.7 181.56,58.62 v182.19,58.62
DRVA11  (via drill 0.3)
  Top 0.254: v182.32,56.85 183.46,57.99 188.04,57.99 v190.07,55.96 190.07,55.45 191.61,53.91 192.85,53.91 v192.97,54.04 | v144.48,55.83 152.1,55.83 152.48,56.21 153.37,56.21 153.62,55.96 153.62,55.19 154.25,54.56 154.51,54.56 | U1.12 155.9,53.17 154.51,54.56 | 154.51,54.56 154.51,55.45 155.14,56.08 156.41,56.08 156.67,56.34 157.81,56.34 158.32,55.83 v167.46,55.83
  Bottom 0.254: v182.32,56.85 180.54,56.85 178.89,55.19 172.02,55.21 171.92,55.21 D20.6 171.29,55.72 170.76,55.19 168.1,55.19 v167.46,55.83 | v190.07,55.96 190.07,57.1 190.31,57.34 D4.6 | D36.6 142.09,55.83 v144.48,55.83 | v192.97,54.04 192.24,53.3 D52.6
DRVA12  (via drill 0.3)
  Top 0.254: v198.96,23.95 200.86,23.95 201.12,24.21 201.12,45.92 200.1,46.94 200.1,58.5 200.86,59.26 v200.86,62.94 200.86,68.15 198.7,70.31 194.77,70.31 194.51,70.56 183.97,70.56 182.19,68.78 v181.05,68.78 181.05,69.16 180.16,70.05 165.3,70.05 163.78,68.53 v153.62,68.53 152.73,68.53 152.48,68.28 v148.79,68.28 | U1.13 155.4,53.03 154.38,54.05 153.62,54.05 152.86,54.81 v152.86,55.45
  Bottom 0.254: v200.86,62.94 200.86,63.2 201.24,63.58 201.24,64.06 D5.4 | D21.4 177.38,66.76 179.4,68.78 v181.05,68.78 | v148.79,68.28 148.79,68.02 148.41,67.64 148.41,65.99 148.16,65.74 148.16,65.38 D37.4 | v198.96,23.95 199.72,23.44 199.72,23.22 D53.4 | v152.86,55.45 153.37,55.96 153.37,60.4 154.89,61.93 154.89,67.26 v153.62,68.53
DRVA13  (via drill 0.3)
  Top 0.254: v149.17,67.26 v153.62,67.26 153.87,67.51 180.92,67.51 v181.05,67.64 181.81,67.64 184.23,70.05 194.26,70.05 194.51,69.8 198.32,69.8 200.1,68.02 v200.1,61.8 200.1,59.13 199.59,58.62 199.59,46.81 200.61,45.8 200.61,25.22 200.36,24.97 v199.21,24.97 | U1.14 154.9,52.9 154.25,53.54 153.24,53.54 v152.22,54.56
  Bottom 0.254: v200.1,61.8 200.1,63.32 200.48,63.7 D5.5 | D21.5 178.13,66.37 179.4,67.64 v181.05,67.64 | v149.17,67.26 148.92,67.01 D37.5 | D53.5 200.48,23.7 v199.21,24.97 | v152.22,54.56 152.22,55.83 152.86,56.46 152.86,60.66 154.38,62.18 154.38,66.5 v153.62,67.26
DRVA14  (via drill 0.3)
  Top 0.254: v149.68,66.37 153.49,66.37 v153.62,66.24 154.38,67.01 180.54,67.01 181.05,66.5 v181.05,66.24 181.18,66.24 184.48,69.55 194.01,69.55 194.26,69.29 198.07,69.29 199.35,68.01 v199.35,60.4 199.1,60.14 199.09,46.56 200.1,45.54 200.1,26.24 v199.72,25.86 | U1.15 154.4,52.76 154.13,53.04 152.22,53.04 v151.59,53.67
  Bottom 0.254: D21.6 178.88,65.72 179.4,66.24 v181.05,66.24 | v149.68,66.37 149.68,65.38 D37.6 | D5.6 199.71,64.07 199.34,63.7 199.34,60.41 v199.35,60.4 | v199.72,25.86 201.12,24.46 201.12,23.32 D53.6 | v151.59,53.67 151.59,55.83 152.35,56.59 152.35,60.91 153.62,62.18 v153.62,66.24
DRVA15  (via drill 0.3)
  Top 0.254: v148.16,88.34 148.41,88.6 177.24,88.6 v177.5,88.34 182.07,88.34 183.46,86.94 196.67,86.94 201.37,82.25 v201.37,77.55 201.75,77.55 202.64,76.66 202.64,59.13 201.63,58.12 201.63,47.32 202.64,46.3 202.64,22.3 200.1,19.76 167.97,19.76 167.46,19.25 v163.65,19.25 | v150.95,52.78 151.63,52.11 U1.16
  Bottom 0.254: D6.4 201.23,77.69 v201.37,77.55 | D38.4 148.16,81 148.16,81.48 149.17,82.5 149.17,85.93 148.16,86.94 v148.16,88.34 148.41,88.6 150.95,88.6 151.21,88.34 151.21,81.99 152.98,80.21 152.98,62.31 151.84,61.16 151.84,56.72 150.95,55.83 v150.95,52.78 | D22.4 177.51,88.33 v177.5,88.34 | D54.4 163.64,19.27 v163.65,19.25
DRVA16  (via drill 0.3)
  Top 0.254: v148.92,87.58 149.43,88.09 176.48,88.09 177.11,87.45 v178.26,87.45 182.32,87.45 183.34,86.44 196.55,86.44 200.48,82.5 v200.48,76.66 201.37,76.66 202.13,75.9 202.13,59.26 201.12,58.24 201.12,47.19 202.13,46.18 202.13,22.56 199.85,20.27 167.46,20.27 167.34,20.14 v162.89,20.14 | U1.17 150.85,51.36 v150.32,51.89
  Bottom 0.254: 200.48,79.45 D6.5 v200.48,76.66 | D22.5 v178.26,87.45 | D38.5 148.92,81.48 149.68,82.25 149.68,86.06 148.92,86.82 v148.92,87.58 149.43,88.09 150.32,88.09 150.7,87.71 150.7,81.61 152.48,79.83 152.48,62.56 151.33,61.42 151.33,56.85 150.32,55.83 v150.32,51.89 | v162.89,20.14 D54.5
DRVA17  (via drill 0.3)
  Top 0.254: v149.68,87.07 150.19,87.58 176.23,87.58 177.37,86.44 v179.02,86.44 182.7,86.44 183.21,85.93 196.42,85.93 199.72,82.63 v199.72,75.9 201.24,75.9 201.63,75.51 201.63,59.39 200.61,58.37 200.61,47.07 201.63,46.05 201.63,22.81 199.59,20.78 167.46,20.78 167.34,20.9 v162.13,20.9 | v149.68,51 149.83,50.86 U1.18
  Bottom 0.254: D6.6 199.73,75.91 v199.72,75.9 | v179.02,86.44 179.02,81 D22.6 | v149.68,87.07 150.19,86.56 150.19,81.86 149.68,81.36 149.68,81 D38.6 149.69,80.98 150.44,80.98 151.97,79.45 151.97,62.81 150.83,61.67 150.83,56.97 149.68,55.83 v149.68,51 | D54.6 162.14,21.04 v162.13,20.9
DRVA18  (via drill 0.3)
  Top 0.254: v181.05,73.23 181.69,72.59 v195.4,72.59 | v167.59,72.59 v157.56,72.59 v150.7,72.59 v143.21,72.59 | v149.05,50.11 149.81,50.11 150.05,50.36 U1.19
  Bottom 0.254: v181.05,73.23 180.4,72.58 D23.4 171.27,72.6 171.27,72.85 170.89,73.23 169.11,73.23 168.48,72.59 v167.59,72.59 | D7.4 194.5,72.58 v195.4,72.59 | D39.4 143.19,72.58 v143.21,72.59 | D55.4 157.54,72.58 v157.56,72.59 | v149.05,50.11 149.05,55.83 150.32,57.1 150.32,61.93 151.46,63.07 151.46,71.83 v150.7,72.59
DRVA19  (via drill 0.3)
  Top 0.254: v194.77,71.83 v181.05,71.83 180.54,72.34 168.86,72.34 168.35,71.83 v158.45,71.83 v149.68,71.83 v144.09,71.83 | v148.41,49.23 149.56,49.23 150.19,49.86 U1.20
  Bottom 0.254: D7.5 v194.77,71.83 | v181.05,71.83 D23.5 | v144.09,71.83 D39.5 | v158.45,71.83 D55.5 | v148.41,49.23 148.41,55.83 149.81,57.23 149.81,62.18 150.95,63.32 150.95,70.56 v149.68,71.83
DRVA20  (via drill 0.3)
  Top 0.254: 182.83,71.07 182.19,70.43 v181.05,70.43 | 182.83,71.07 v195.4,71.08 | 188.02,71.07 182.83,71.07 | v167.59,71.07 v157.56,71.07 v148.79,71.07 v143.21,71.07 | U1.21 150.31,49.36 150.32,49.35 149.3,48.34 v147.78,48.34
  Bottom 0.254: v181.05,70.43 180.4,71.08 D23.6 171.27,71.07 171.27,70.56 171.15,70.43 169.24,70.43 168.61,71.07 v167.59,71.07 | v195.4,71.08 D7.6 | D39.6 143.19,71.08 v143.21,71.07 | v157.56,71.07 156.57,71.07 D55.6 | v147.78,48.34 147.78,55.96 149.3,57.48 149.3,62.43 150.44,63.58 150.44,69.42 v148.79,71.07
DRVA21  (via drill 0.3)
  Top 0.254: v72.47,91.77 73.99,91.77 74.63,92.41 86.82,92.41 v87.58,91.64 89.36,91.64 90.12,92.41 115.9,92.41 v116.28,92.02 116.41,91.9 127.97,91.9 128.09,91.77 v130.51,91.77 | U1.22 150.46,48.86 149.3,47.7 146.89,47.7 v145.75,48.84 139.78,54.81 v130.89,54.81
  Bottom 0.254: D8.4 117.67,86.45 116.66,87.45 116.66,91.64 v116.28,92.02 | D24.4 88.33,86.45 87.58,87.2 v87.58,91.64 | D40.4 68.15,87.96 69.16,88.98 72.21,88.98 72.45,89.22 72.48,89.22 v72.47,91.77 | v130.89,54.81 130.51,55.19 v130.51,91.77 | D56.4 142.81,45.91 v145.75,48.84
DRVA22  (via drill 0.3)
  Top 0.254: v73.1,92.53 74.12,92.53 74.5,92.91 87.96,92.91 v88.34,92.53 89.48,92.53 89.87,92.91 116.79,92.91 v116.92,92.79 117.17,92.53 v129.49,92.53 | v130.38,53.92 139.4,53.92 v145.87,47.45 146.13,47.19 149.43,47.19 150.59,48.36 U1.23
  Bottom 0.254: D8.5 118.06,87.2 117.17,88.09 117.17,92.53 v116.92,92.79 | D24.5 88.72,87.2 88.34,87.58 v88.34,92.53 | D40.5 68.66,87.2 69.93,88.47 72.85,88.47 73.23,88.85 73.23,92.41 v73.1,92.53 | v129.49,92.53 129.49,91.64 130,91.14 130,54.31 v130.38,53.92 | D56.5 143.59,45.16 v145.87,47.45
DRVA23  (via drill 0.3)
  Top 0.254: v73.74,93.29 73.86,93.42 88.6,93.42 88.72,93.29 v89.1,93.29 89.48,93.29 89.61,93.42 116.15,93.42 116.28,93.55 117.3,93.55 117.55,93.29 v117.81,93.29 v128.73,93.29 | U1.24 150.73,47.86 149.56,46.69 145.62,46.69 | 145.62,46.69 145.36,46.69 139.01,53.04 v129.49,53.04 | 145.62,46.69 v145.62,45.92
  Bottom 0.254: D8.6 118.2,87.95 117.68,88.47 117.68,93.17 v117.81,93.29 | D40.6 69.05,86.45 69.67,87.07 69.67,87.33 70.31,87.96 73.1,87.96 73.74,88.6 v73.74,93.29 | v129.49,53.04 129.49,90.63 128.73,91.39 v128.73,93.29 | D56.6 144.11,44.41 v145.62,45.92 | D24.6 89.12,93.28 v89.1,93.29
DRVB0  (via drill 0.3)
  Top 0.254: v110.44,90.5 110.31,90.63 90.5,90.63 89.74,89.87 86.69,89.87 86.18,90.37 80.85,90.37 v80.59,90.63 80.34,90.88 75.01,90.88 72.72,88.6 70.94,88.6 70.18,89.36 v70.18,91.01 | U2.1 108.63,49.25 109.3,48.59 v110.31,48.59 | v114,29.16 113.87,29.16 112.73,30.3 112.73,38.43 v112.47,38.68
  Bottom 0.254: v110.44,90.5 109.8,89.87 109.8,82.12 110.58,81.34 D9.4 110.56,80.98 109.8,80.98 108.79,79.96 108.79,70.69 107.26,69.16 107.26,63.07 112.6,57.73 112.6,50.11 111.07,48.59 v110.31,48.59 110.31,46.81 112.47,44.65 v112.47,38.68 | v80.59,90.63 80.59,81.86 81.23,81.23 81.23,81 D25.4 | D41.4 59.14,81.24 59.13,81.61 59.13,87.45 61.04,89.36 65.48,89.36 66.62,90.5 69.67,90.5 v70.18,91.01 | D57.4 114.01,29.17 v114,29.16
DRVB1  (via drill 0.3)
  Top 0.254: v111.2,91.14 111.07,91.26 90.5,91.26 89.61,90.37 86.82,90.37 85.8,91.39 83.39,91.39 82.88,90.88 81.74,90.88 v81.48,91.14 81.23,91.39 74.88,91.39 72.85,89.36 71.07,89.36 70.82,89.61 70.82,90.25 v71.58,91.01 | U2.2 110.8,49.75 v110.82,49.73 111.2,49.35 v111.2,47.19 | v114.63,29.92 114,30.56 114,31.19 114.76,31.95 114.76,34.62 115.27,35.13 115.27,38.56 v115.14,38.68
  Bottom 0.254: D9.5 111.33,81.48 110.31,82.5 110.31,89.36 111.33,90.37 111.33,91.01 v111.2,91.14 110.95,91.39 109.8,91.39 108.28,89.87 108.28,70.94 106.76,69.42 106.76,62.94 112.09,57.61 112.09,50.62 111.2,49.73 v110.82,49.73 | v81.48,91.14 81.48,90.12 81.1,89.74 81.1,82.37 81.99,81.48 D25.5 | D41.5 59.89,81.61 59.64,81.86 59.64,86.94 61.29,88.6 65.48,88.6 66.88,89.99 70.56,89.99 v71.58,91.01 | v114.63,29.92 D57.5 | v115.14,38.68 115.14,42.62 111.2,46.56 v111.2,47.19
DRVB2  (via drill 0.3)
  Top 0.254: v112.09,91.52 112.09,91.64 111.84,91.9 90.37,91.9 89.36,90.88 87.07,90.88 86.06,91.9 82.75,91.9 v82.5,91.64 82.25,91.9 74.75,91.9 72.97,90.12 v71.83,90.12 | U2.3 110.2,50.25 v110.82,50.88 112.34,49.35 v112.34,48.34 | v115.01,30.94 115.01,31.19 115.27,31.45 115.27,34.24 116.15,35.13 v116.15,38.68
  Bottom 0.254: D9.6 112.08,81.62 110.82,82.88 110.82,89.1 112.09,90.37 v112.09,91.52 | v112.09,91.52 112.08,91.5 | D25.6 82.74,81.5 81.61,82.63 81.61,89.48 82.5,90.37 82.49,91.27 v82.5,91.64 | D41.6 60.64,81.62 60.15,82.12 60.15,86.56 61.54,87.96 65.61,87.96 67.13,89.48 71.2,89.48 v71.83,90.12 | v110.82,50.88 111.58,51.64 111.58,57.48 106.25,62.81 106.25,69.55 107.77,71.07 107.77,90.75 108.92,91.9 111.71,91.9 v112.09,91.52 | D57.6 115.28,30.67 v115.01,30.94 | v116.15,38.68 116.15,42.24 112.34,46.05 v112.34,48.34
DRVB3  (via drill 0.3)
  Top 0.254: v110.31,66.37 110.19,66.5 107.52,66.5 106.38,65.35 v105.61,65.35 102.95,65.35 101.8,66.5 99.26,66.5 98.63,65.86 95.07,65.86 94.31,66.62 83.77,66.62 83.13,65.99 81.48,65.99 v81.1,66.37 80.85,66.62 77.29,66.62 76.91,66.24 65.99,66.24 61.04,61.29 v60.15,61.29 | U2.4 109.68,50.75 110.82,51.89 v110.82,52.65 | v60.02,50.88 v61.42,50.88
  Bottom 0.254: D10.4 110.58,66.1 v110.31,66.37 | v81.1,66.37 81.1,66.12 81.23,65.99 81.23,65.38 D26.4 | v110.82,52.65 110.82,57.61 105.61,62.81 v105.61,65.35 | D58.4 65.22,44.41 60.02,49.61 v60.02,50.88 | v61.42,50.88 61.42,51.13 60.15,52.4 v60.15,61.29 60.27,61.42 60.27,63.32 60.52,63.56 D42.4
DRVB4  (via drill 0.3)
  Top 0.254: v111.2,66.75 110.95,67.01 107.26,67.01 106.5,66.24 v105.23,66.24 102.69,66.24 101.93,67.01 99.01,67.01 98.37,66.37 95.33,66.37 94.56,67.13 83.64,67.13 83.13,66.62 82.12,66.62 v81.99,66.75 81.61,67.13 77.17,67.13 76.78,66.75 65.74,66.75 61.04,62.05 v59.39,62.05 | U2.5 109.29,51.25 110.06,52.02 110.06,53.67 v110.19,53.8
  Bottom 0.254: D10.5 111.33,66.62 v111.2,66.75 | v81.99,66.75 D26.5 | D42.5 59.77,62.43 v59.39,62.05 59.39,52.53 60.78,51.13 60.78,49.86 65.48,45.16 D58.5 | v110.19,53.8 110.19,57.61 104.98,62.81 104.98,65.99 v105.23,66.24
DRVB5  (via drill 0.3)
  Top 0.254: v104.72,67.13 102.69,67.13 102.31,67.51 98.76,67.51 98.12,66.88 96.34,66.88 95.58,67.64 83.01,67.64 v82.75,67.39 82.5,67.64 77.04,67.64 76.66,67.26 65.48,67.26 61.29,63.07 59.13,63.07 v59.02,63.06 | v104.72,67.13 103.84,67.13 | U2.6 109.03,51.75 109.55,52.27 v109.55,54.69 | v104.72,67.13 106.63,67.13 107.14,67.64 111.71,67.64 v112.09,67.26 | v61.8,51.77 v58.88,51.77
  Bottom 0.254: v112.09,67.26 112.08,67.25 D10.6 112.09,65.35 | v82.75,67.39 82.75,65.38 D26.6 | D42.6 v59.02,63.06 59.02,62.7 58.62,62.31 58.62,51.77 v58.88,51.77 | v104.72,67.13 104.47,66.88 104.47,62.69 109.55,57.61 v109.55,54.69 | v61.8,51.77 62.18,51.38 62.18,49.35 65.61,45.92 66.85,45.92 D58.6
DRVB6  (via drill 0.3)
  Top 0.254: v69.16,57.35 70.31,57.35 71.2,56.46 89.99,56.46 90.88,57.35 v91.52,57.35 95.2,57.35 97.87,60.02 v106.12,60.02 111.58,60.02 114.25,57.35 v120.85,57.35 | U2.7 108.64,52.25 108.79,52.4 v108.79,53.8 | v92.91,52.4 87.71,52.4 v86.94,53.16
  Bottom 0.254: D43.4 69.41,57.34 v69.16,57.35 | v120.85,57.35 119.74,57.35 D11.4 | v106.12,60.02 106.5,60.02 108.79,57.73 v108.79,53.8 | D59.4 87.69,44.54 86.94,45.29 v86.94,53.16 | 90.5,57.36 D27.4 90.53,57.35 v91.52,57.35 92.53,57.35 93.04,56.85 93.04,52.53 v92.91,52.4
DRVB7  (via drill 0.3)
  Top 0.254: v69.93,56.59 70.56,55.96 90.37,55.96 91.01,56.59 v92.28,56.59 95.33,56.59 97.99,59.26 106.25,59.26 v106.38,59.13 106.63,59.26 111.33,59.26 114,56.59 v121.36,56.59 | U2.8 108,54.66 v108.03,54.69 | v92.28,53.16 v88.09,53.16
  Bottom 0.254: D43.5 v69.93,56.59 | D27.5 v92.28,56.59 v92.28,53.16 | v121.36,56.59 D11.5 | v106.38,59.13 106.76,59.13 108.28,57.61 108.28,54.94 v108.03,54.69 | D59.5 88.6,45.29 88.09,45.8 v88.09,53.16
DRVB8  (via drill 0.3)
  Top 0.254: v69.16,55.83 69.55,55.45 91.01,55.45 v91.52,55.83 95.2,55.83 97.87,58.5 105.87,58.5 105.99,58.37 107.14,58.37 | 107.14,58.37 111.33,58.37 113.87,55.83 v120.85,55.83 | U2.9 107.24,58.27 107.14,58.37
  Bottom 0.254: D43.6 69.41,55.84 v69.16,55.83 | v91.52,55.83 90.53,55.83 D27.6 90.5,55.83 90.5,52.78 89.22,51.5 89.1,51.38 89.1,46.05 D59.6 | v120.85,55.83 119.74,55.83 D11.6
DRVB9  (via drill 0.3)
  Top 0.254: v74.12,68.15 74.5,67.77 76.53,67.77 76.91,68.15 96.09,68.15 v96.6,67.64 96.85,67.39 97.99,67.39 98.76,68.15 103.07,68.15 v103.2,68.02 106.76,68.02 106.88,68.15 125.04,68.15 v125.43,67.77 125.43,60.53 v126.06,59.89 | U2.10 106.74,55.98 v105.74,56.97
  Bottom 0.254: v125.43,67.77 125.82,67.37 D12.4 125.8,65.35 | v74.12,68.15 74.37,67.89 74.37,65.38 D44.4 | D28.4 96.61,67.12 v96.6,67.64 | v103.2,68.02 103.07,67.89 103.07,59.64 v105.74,56.97 | D60.4 125.82,39.2 126.31,39.7 126.31,59.64 v126.06,59.89
DRVB10  (via drill 0.3)
  Top 0.254: v75.01,68.66 75.26,68.4 76.4,68.4 76.66,68.66 96.98,68.66 v97.36,68.28 98.12,68.28 98.5,68.66 102.44,68.66 v102.69,68.91 104.22,68.91 104.47,68.66 126.06,68.66 v126.31,68.4 126.82,67.77 v126.82,60.53 | U2.11 106.24,55.46 v104.72,56.97
  Bottom 0.254: D12.5 126.57,68.15 v126.31,68.4 | D44.5 75.13,68.53 v75.01,68.66 | v97.36,68.28 D28.5 | v102.69,68.91 102.57,68.78 102.57,59.13 v104.72,56.97 | D60.5 126.57,39.19 126.82,39.45 v126.82,60.53
DRVB11  (via drill 0.3)
  Top 0.254: v75.9,69.16 v97.74,69.16 101.55,69.16 v102.18,69.8 104.09,69.8 104.72,69.16 v127.08,69.16 127.58,68.66 v127.58,59.89 | 105.74,54.94 U2.12 | 105.74,54.94 | 105.74,54.94 104.22,56.46 103.71,56.46 103.45,56.72 v103.45,56.97
  Bottom 0.254: D12.6 127.32,68.92 v127.08,69.16 | v75.9,69.16 75.9,65.38 D44.6 | D28.6 98.11,68.8 v97.74,69.16 | v103.45,56.97 102.06,58.37 102.06,69.67 v102.18,69.8 | D60.6 127.33,38.71 127.33,59.64 v127.58,59.89
DRVB12  (via drill 0.3)
  Top 0.254: v125.68,86.18 122.5,89.36 120.85,89.36 120.47,88.98 111.96,88.98 111.71,88.72 109.17,88.72 108.92,88.98 103.45,88.98 v103.2,88.72 102.95,88.47 96.34,88.47 v96.22,88.6 95.83,88.98 90.75,88.98 90.12,88.34 85.93,88.34 85.42,88.85 76.66,88.85 76.53,88.72 74.63,88.72 v74.37,88.98 | U2.13 105.24,54.68 103.96,55.96 102.95,55.96 102.31,56.59 v102.31,56.97 102.31,57.35 101.68,57.99 98.63,57.99 96.6,55.96 96.6,55.32 v96.09,54.81
  Bottom 0.254: D13.4 125.95,85.92 v125.68,86.18 | D29.4 96.61,88.2 v96.22,88.6 | v74.37,88.98 75.77,87.58 75.77,82.88 74.37,81.48 74.37,81 D45.4 | v102.31,56.97 101.55,57.73 101.55,75.01 105.87,79.32 105.87,85.55 103.2,88.21 v103.2,88.72 | D61.4 96.61,52.9 96.09,53.42 v96.09,54.81
DRVB13  (via drill 0.3)
  Top 0.254: v125.93,87.2 123.27,89.87 120.6,89.87 120.22,89.48 111.71,89.48 111.46,89.23 109.42,89.23 109.17,89.48 102.57,89.48 v102.31,89.23 102.06,88.98 97.49,88.98 v97.1,89.36 96.98,89.48 90.63,89.48 89.99,88.85 86.18,88.85 85.67,89.36 80.09,89.36 79.58,89.87 77.04,89.87 76.4,89.23 75.51,89.23 v75.13,89.61 | U2.14 104.74,54.42 103.71,55.45 102.44,55.45 v101.55,56.34 101.55,56.97 101.04,57.48 99.14,57.48 97.49,55.83 97.49,54.81 96.85,54.18 v96.85,54.05
  Bottom 0.254: D13.5 126.7,86.44 v125.93,87.2 | D29.5 97.36,89.1 v97.1,89.36 | v75.13,89.61 76.28,88.47 76.28,82.63 75.13,81.48 D45.5 | v101.55,56.34 101.04,56.85 101.04,75.26 105.36,79.58 105.36,85.29 102.31,88.34 v102.31,89.23 | D61.5 97.36,53.54 v96.85,54.05
DRVB14  (via drill 0.3)
  Top 0.254: v126.19,88.21 124.03,90.37 120.35,90.37 119.96,89.99 111.33,89.99 111.07,89.74 109.8,89.74 109.55,89.99 v101.3,89.99 v97.87,89.99 90.5,89.99 89.87,89.36 86.44,89.36 85.93,89.87 80.34,89.87 79.83,90.37 76.4,90.37 v76.15,90.12 | U2.15 104.24,54.03 103.33,54.94 101.55,54.94 v100.79,55.7 100.79,56.46 100.28,56.97 99.52,56.97 98.37,55.83 98.37,54.31 v97.99,53.92
  Bottom 0.254: D13.6 127.45,86.93 v126.19,88.21 | v97.87,89.99 98.11,89.75 D29.6 98.12,80.98 | v76.15,90.12 76.78,89.48 76.78,82.37 75.9,81.48 75.9,81 D45.6 | v100.79,55.7 100.53,55.96 100.53,75.51 104.85,79.83 104.85,85.04 101.3,88.6 v101.3,89.99 | v97.99,53.92 97.99,38.81 D61.6
DRVB15  (via drill 0.3)
  Top 0.254: v69.29,72.59 v91.64,72.59 v99.77,72.59 v106.25,72.59 v120.98,72.59 | U2.16 101.72,53.5 v100.53,54.69
  Bottom 0.254: D46.4 69.03,72.58 v69.29,72.59 | v120.98,72.59 119.74,72.59 D14.4 | D30.4 91.38,72.58 v91.64,72.59 | D62.4 106.11,72.58 v106.25,72.59 | v99.77,72.59 100.03,72.34 100.03,55.19 v100.53,54.69
DRVB16  (via drill 0.3)
  Top 0.254: v69.8,71.83 v92.15,71.83 v99.01,71.83 v106.76,71.83 v121.74,71.83 | U2.17 101.07,52.75 v99.77,54.05
  Bottom 0.254: v121.74,71.83 D14.5 | D46.5 v69.8,71.83 | v92.15,71.83 D30.5 | v106.76,71.83 D62.5 | v99.01,71.83 99.52,71.32 99.52,54.31 v99.77,54.05
DRVB17  (via drill 0.3)
  Top 0.254: v69.29,71.07 v91.64,71.07 v98.25,71.07 v106.25,71.07 v120.98,71.07 | U2.18 100.17,52.25 v99.01,53.42
  Bottom 0.254: D14.6 120.97,71.08 v120.98,71.07 | v91.64,71.07 90.53,71.07 D30.6 | v69.29,71.07 68.18,71.07 D46.6 | D62.6 106.11,71.08 v106.25,71.07 | v99.01,53.42 99.01,70.31 v98.25,71.07
DRVB18  (via drill 0.3)
  Top 0.254: v9.35,78.82 v21.79,78.82 v34.37,78.82 v46.96,78.82 | U2.19 96.23,51.75 93.04,54.94 52.27,54.94 51.26,55.96 51.26,75.39 47.83,78.82 v46.96,78.82 | v46.96,78.82 v46.95,78.83
  Bottom 0.254: v46.95,78.83 D15.4 | v9.35,78.82 8.43,78.82 D63.4 | D47.4 20.79,78.83 v21.79,78.82 | D31.4 33.24,78.83 v34.37,78.82
DRVB19  (via drill 0.3)
  Top 0.254: v9.98,78.05 v22.43,78.05 v35,78.05 v47.57,78.05 50.75,74.88 50.75,55.83 52.15,54.43 92.91,54.43 96.09,51.25 U2.20
  Bottom 0.254: D63.5 v9.98,78.05 | v47.57,78.05 D15.5 | v22.43,78.05 D47.5 | v35,78.05 D31.5
DRVB20  (via drill 0.3)
  Top 0.254: v9.35,77.29 v21.79,77.29 v34.37,77.29 v46.94,77.29 47.57,77.29 50.24,74.63 50.24,55.7 52.02,53.92 92.79,53.92 95.96,50.75 U2.21
  Bottom 0.254: D63.6 8.34,77.28 v9.35,77.29 | v46.94,77.29 45.82,77.29 D15.6 | D47.6 20.79,77.28 v21.79,77.29 | D31.6 33.36,77.28 v34.37,77.29
DRVB21  (via drill 0.3)
  Top 0.254: U2.22 95.82,50.25 94.44,51.64 87.33,51.64 85.55,53.42 51.89,53.42 49.73,55.58 49.73,65.23 48.59,66.37 v46.81,66.37 v34.37,66.37 v21.79,66.37 v9.35,66.37
  Bottom 0.254: D64.4 8.34,66.38 v9.35,66.37 | v46.81,66.37 45.77,66.37 D16.4 | D32.4 33.36,66.38 v34.37,66.37 | D48.4 21.78,66.36 v21.79,66.37
DRVB22  (via drill 0.3)
  Top 0.254: v9.98,65.61 v22.43,65.61 v35,65.61 35.26,65.86 46.43,65.86 46.69,65.61 v47.45,65.61 48.34,65.61 49.23,64.72 49.23,55.19 51.51,52.91 85.42,52.91 87.2,51.13 94.31,51.13 95.69,49.75 U2.23
  Bottom 0.254: v47.45,65.61 D16.5 | D64.5 v9.98,65.61 | v22.43,65.61 D48.5 | v35,65.61 D32.5
DRVB23  (via drill 0.3)
  Top 0.254: U2.24 95.55,49.25 94.18,50.62 87.07,50.62 85.29,52.4 51.26,52.4 48.72,54.94 48.72,63.83 47.7,64.85 v46.81,64.85 46.3,65.35 36.78,65.35 36.27,64.85 v34.37,64.85 v21.79,64.85 v9.35,64.85
  Bottom 0.254: D64.6 8.47,64.83 v9.35,64.85 | v46.81,64.85 45.77,64.85 D16.6 | D32.6 33.36,64.83 v34.37,64.85 | D48.6 21.78,64.86 v21.79,64.85
GND  (via drill 0.3)
  Top 0.254: R1.1 C1.2 157.15,44.89 156.37,45.67 156.03,45.67 155.9,45.8 U1.29 155.9,49.36 U1.PAD | 184.73,40.21 184.23,39.71 U3.3 | 184.73,40.21 185.62,40.21 186.13,39.7 186.13,39.32 186.39,39.07 187.54,39.07 187.97,39.49 C11.2 | 193.24,40.21 192.74,39.71 U5.3 | 193.24,40.21 194.26,40.21 194.64,39.83 194.64,39.45 195.02,39.07 196.18,39.07 196.61,39.49 C13.2 | v183.21,41.73 184.23,41.73 184.48,41.48 184.48,40.46 184.73,40.21 | 193.24,40.21 193.12,40.34 193.12,40.97 192.35,41.73 192.35,43.38 192.86,43.89 | 187.91,50.75 v190.2,50.75 190.58,51.13 192.43,51.13 192.44,51.14 U6.3 193,51.14 193.5,51.64 194.51,51.64 194.77,51.38 194.77,50.75 194.89,50.62 195.93,50.62 196.61,51.31 C14.2 | 187.91,50.75 186.26,50.75 186,51 186,51.64 185.75,51.89 184.61,51.89 184.11,51.39 U4.3 | U15.6 88.34,37.8 86.88,36.34 C30.2 | U14.10 121.9,47.68 v122,47.57 | v124.28,46.3 C29.2 123.2,45.46 123.03,45.29 121.11,45.29 121.11,45.54 120.35,46.3 U14.8 U14.EP | U12.10 55.04,74.27 54.31,75.01 54.31,75.37 C28.2 | U2.PAD 105.74,50.75 U2.29 105.74,47.16 106.86,46.04 C2.2 106.88,45.84 v106.88,44.78 | v98.88,48.08 R2.1 | U12.EP U12.8 56.72,77.42 55.19,78.94 53.92,78.94 53.29,79.58 | U11.EP@1 9.53,89.04 U11.EP@7 | U11.EP@9 10.18,89.04 U11.EP@2 10.18,87.38 | U11.EP@3 9.53,90.19 U11.EP@8 | U11.EP@4 10.18,90.19 U11.EP@10 | C16.2 14.48,90.26 | 12.27,85.59 C18.2 13.16,85.55 13.79,84.91 13.79,83.77 14.3,83.26 46.94,83.26 47.83,84.15 47.83,92.28 49.73,94.18 64.72,94.18 66.12,92.79 66.12,77.67 68.91,74.88 116.54,74.88 116.92,74.5 122.89,74.5 124.03,73.36 132.54,73.36 136.22,77.04 136.22,78.82 135.86,79.17 C36.2
  Top 0.254: R39.1 R42.1 128.88,82.65 128.6,82.37 U13.4 | U13.6 130,75.82 130,78.63 | C12.2 187.97,50.81 187.91,50.75 | U7.EP U7.2
  Top 0.305: U11.EP@10 10.43,89.94 U11.7 12.96,89.94 C15.2
  Top 0.381: C20.2 35.09,56.46 36.78,56.46 38.56,54.69 C38.2 41.22,54.7 v41.22,53.54 | C37.2 50.75,51.13 47.7,54.18 v47.83,54.18 | 9.47,48.21 9.73,48.46 C40.2 15.82,48.45 15.82,47.57 16.08,47.32 19.63,47.32 19.95,47.64 C39.2 | v2.24,89.36 C41.2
